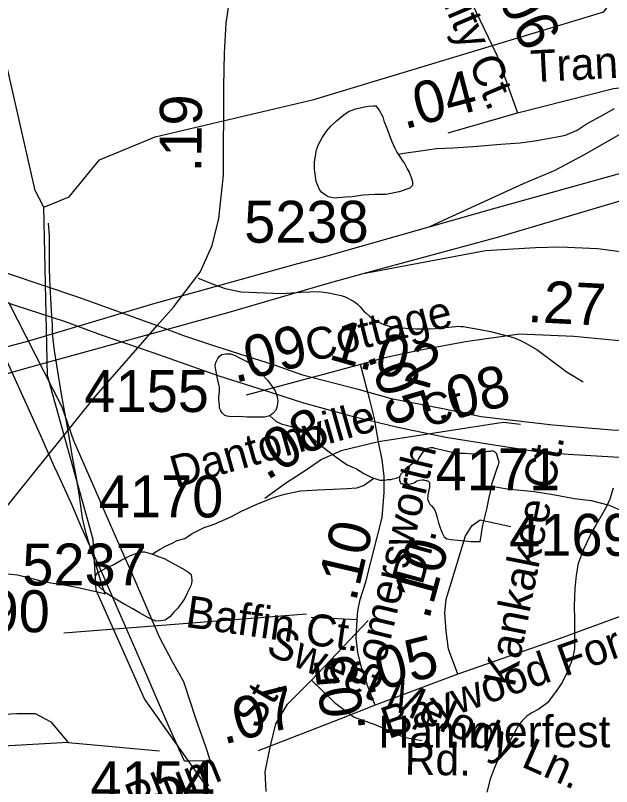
# Model space of a CAD drawing. Extents: x 2169602 to 2449496, y 721995 to 810662.
# Drawn here: x 2396320 to 2398099, y 797480 to 799779 of the extents above; entities that cross this region are included whole.
import ezdxf

# ---------------------------------------------------------------- set-up
doc = ezdxf.new("R2010")
doc.units = 0
doc.layers.add('Default', color=7, linetype='Continuous')

msp = doc.modelspace()

# ---------------------------------------------------------------- linework, layer by layer
at = {"layer": 'Default'}
for p, q in [((2397188.4, 797994.3), (2396464.8, 797937.6)), ((2397339.9, 797977.5), (2397202.8, 797984)), ((2397203.4, 797797.3), (2397373.3, 797974.6)), ((2397640.3, 797814.8), (2397394, 797722.3)), ((2396477.3, 797611.4), (2396184.4, 797594.2)), ((2396477.3, 797611.4), (2396750.5, 797586.8))]:
    msp.add_line(p, q, dxfattribs=at)
for points in [[(2396405.1, 799207.2), (2396379.1, 799256.9), (2396191.1, 800080.9), (2396072.1, 800611.5), (2396037.1, 800828.7)], [(2397623.6, 799980.6), (2397667.1, 799847.6), (2397757.1, 799660.2), (2397818.6, 799488.1)], [(2396848.5, 798983.4), (2396871.3, 799013.1), (2396906.9, 799092.7), (2396927.3, 799173.3), (2396940.9, 799303.1), (2396942.4, 799568), (2396944.5, 799666.5), (2396948.8, 799756.1), (2396958, 799816.4), (2396968.9, 799884.8), (2396980.5, 799945.6)], [(2396405.1, 799207.2), (2396480.2, 799238.4), (2396571, 799348.1), (2396737.1, 799416.9), (2397211.2, 799528.6), (2398076.1, 799789.8), (2398151.3, 799892.8)], [(2397554.8, 799148.4), (2397623.6, 799180.7), (2397836, 799278.1), (2397930.6, 799317.2), (2398018.5, 799364.5), (2398135.2, 799430.9), (2398287.1, 799527.8), (2398366, 799581.1), (2398521.2, 799685.1), (2398585.6, 799724.2), (2398595.1, 799729.4), (2398620.6, 799743.8)], [(2397818.6, 799488.1), (2398104.9, 799561.2), (2398193.7, 799571.1), (2398260.8, 799573), (2398391.1, 799537.5), (2398462.2, 799500), (2398545.1, 799438.7), (2398608.3, 799349.9), (2398742.5, 799144.4), (2398864.9, 798962.7), (2398898.5, 798893)], [(2397462.5, 799365.4), (2397466.6, 799359.5), (2397475, 799345.2), (2397481, 799337.4), (2397489, 799321.6), (2397494.9, 799311.4), (2397501.1, 799295.4), (2397505, 799283.5), (2397505.2, 799279.4), (2397505.2, 799271.7), (2397497.6, 799263.5), (2397465.2, 799253.4), (2397425.6, 799245.2), (2397393.2, 799244.8), (2397357.7, 799242.9), (2397325.5, 799238.4), (2397305.6, 799236.6), (2397271.6, 799234), (2397253.6, 799238.3), (2397241.3, 799246.3), (2397233.3, 799252), (2397227.5, 799260.2), (2397217.5, 799283.9), (2397215, 799305.8), (2397213.2, 799319.9), (2397213, 799341.8), (2397217.1, 799366), (2397218.7, 799377.9), (2397224.7, 799394), (2397236.5, 799416.2), (2397248.4, 799434.3), (2397262.6, 799449.9), (2397278, 799464.2), (2397300.1, 799482.4), (2397314.3, 799492.4), (2397336, 799500.5), (2397362, 799506.7), (2397373.7, 799508.6), (2397387.9, 799508.9), (2397396.1, 799508.9), (2397405.9, 799496.8), (2397416.2, 799477), (2397420.1, 799465.1), (2397428.5, 799443.1), (2397442.4, 799405.3), (2397452.9, 799383), (2397458.8, 799371.2), (2397462.5, 799365.4)], [(2397462.5, 799365.4), (2397486.7, 799369.4), (2397529, 799375.6), (2397576.7, 799381.8), (2397626.8, 799384.3), (2397686.6, 799388.6), (2397768.5, 799394.9), (2397826.5, 799399.5), (2397876.5, 799405.8), (2397942.3, 799418.2), (2397962, 799422.1), (2397996.3, 799436.4), (2398023.9, 799454.4), (2398074.2, 799482.5), (2398107.8, 799501)], [(2397554.8, 799148.4), (2397754.8, 799205.1), (2398512.4, 799416), (2398798.3, 799498.8)], [(2397611.3, 799428.9), (2397818.6, 799488.1)], [(2397358.4, 799009.7), (2397763.2, 799118.4), (2398299.3, 799277.7), (2398688.2, 799382), (2398860.6, 799432)], [(2395355.1, 799242.6), (2395483.4, 799218.7), (2395640.2, 799190.2), (2395732.9, 799171), (2395883.1, 799133.6), (2395992.3, 799104.3), (2396146.4, 799059.4), (2396301.6, 799008.2), (2396508.9, 798939.4), (2396743.6, 798854.3)], [(2397643, 796796.9), (2397442.1, 797053.6), (2397233.1, 797185.9), (2397032.2, 797226), (2396949.1, 797326.2), (2396906.1, 797458.2), (2396705.1, 797741.2), (2396561.2, 798065.7), (2396552.2, 798216.7), (2396416.2, 798705), (2396405.1, 799207.2)], [(2397358.4, 799009.7), (2397723.5, 799077.7), (2397871.9, 799086.7), (2397944.6, 799088.7), (2398056.9, 799084.1), (2398194.1, 799066.6), (2398376, 799039.8), (2398559, 799012.3), (2398652.2, 799004.3), (2398738.4, 799007.7), (2398822.4, 799020.5), (2398883.6, 799038.5), (2398949.7, 799061.3), (2399012.6, 799095.9), (2399120.1, 799184.7), (2399154.1, 799209.3)], [(2396417.9, 799159.4), (2396420.5, 799121.7), (2396420.7, 799053.5), (2396420.9, 799021.4), (2396423.2, 798969.6), (2396425.6, 798917.7), (2396427.7, 798881.6), (2396430.2, 798857.7), (2396429.7, 798835.5), (2396432.2, 798813.7), (2396436.3, 798779.8), (2396442.5, 798735.8), (2396446.6, 798711.6), (2396457, 798649.6), (2396471.6, 798568), (2396481.8, 798512), (2396490, 798462.1), (2396500.3, 798406.2), (2396510.7, 798346.2), (2396519.4, 798280.4), (2396529.2, 798238.3), (2396541.7, 798198.4), (2396560.2, 798140.4), (2396580.3, 798074.5), (2396588.5, 798054.6)], [(2393727.7, 798967.2), (2393806.4, 798937.7), (2393895.5, 798907.3), (2393994.7, 798875.9), (2394073.5, 798850.7), (2394160.7, 798819.8), (2394322.8, 798778.6), (2394425.4, 798749.4), (2394579.5, 798719.5), (2394694.5, 798696.6), (2394908.4, 798671.3), (2395084.1, 798656.4), (2395222, 798655), (2395369.2, 798660.5), (2395553.8, 798663.3), (2395797.4, 798685), (2395992.3, 798720.4), (2396192.5, 798764.3), (2396360.4, 798808.9), (2396730.4, 798919.4), (2397163.3, 799039.1), (2397250.8, 799062.3), (2397554.8, 799148.4)], [(2395411.2, 799149.2), (2395451.8, 799142.5), (2395632, 799110.5), (2395732.9, 799087.6), (2395895, 799042), (2396137.2, 798975.1), (2396318.1, 798914.7), (2396468.5, 798866.1), (2396573.3, 798827.7), (2396686.6, 798789.3)], [(2396743.6, 798854.3), (2396822.3, 798824.9), (2396911.3, 798794.5), (2397010.6, 798763), (2397089.3, 798737.9), (2397176.5, 798707), (2397338.6, 798665.8), (2397441.3, 798636.6), (2397595.3, 798606.7), (2397710.3, 798583.7), (2397924.2, 798558.4), (2398099.9, 798543.6), (2398237.8, 798542.2), (2398385, 798547.7), (2398569.6, 798550.5), (2398813.2, 798572.1), (2399008.1, 798607.5), (2399208.3, 798651.5), (2399376.3, 798696), (2399746.2, 798806.6), (2400179.1, 798926.3), (2400266.6, 798949.5), (2400570.6, 799035.6)], [(2396170.5, 798675.2), (2396355.1, 798728.5), (2396652.2, 798810.1), (2396958, 798894.6), (2397250.8, 798980.2), (2397358.4, 799009.7)], [(2396865.8, 798996), (2396917.9, 798974.4), (2396945.9, 798964.6), (2396994.1, 798955.2), (2397114.2, 798950.3), (2397158.2, 798952.8), (2397172.3, 798953.7), (2397226.1, 798955.6), (2397254.6, 798952.1), (2397292.3, 798944.3), (2397304.2, 798939.8), (2397314.1, 798935), (2397321.4, 798931.5), (2397329.1, 798926.7), (2397335.2, 798922.6), (2397340.9, 798918.3), (2397349.5, 798910.1), (2397359.3, 798898.7), (2397366.8, 798891.2), (2397376.4, 798882), (2397385, 798875.4), (2397391.7, 798871.1), (2397404.4, 798864.6), (2397416.7, 798858.9), (2397425.6, 798855.6), (2397436.9, 798852.1), (2397447.3, 798849.9), (2397462.5, 798848), (2397485.4, 798846.3), (2397515.4, 798844.7), (2397534, 798844.3), (2397556, 798844.5), (2397573.4, 798845.3), (2397613.3, 798849.7), (2397643.3, 798852.1), (2397649.9, 798852), (2397656.5, 798851.4), (2397667.1, 798849.6), (2397707.5, 798842.8), (2397737.6, 798837), (2397795.7, 798821.6), (2397811.2, 798816.5), (2397827.8, 798809.9), (2397839.9, 798803.9), (2397876.1, 798782.5), (2397916.4, 798752.9), (2397966.9, 798715.5), (2398014.7, 798686.3)], [(2396743.6, 798854.3), (2396791.8, 798909.4), (2396848.5, 798983.4)], [(2396299.2, 798924.3), (2396458.7, 798612.1), (2396493.4, 798511.5), (2396550.7, 798382.4), (2396590.4, 798290.6), (2396631.9, 798196), (2396672.9, 798104.3), (2396749.2, 797926.5), (2396788.4, 797852.9), (2396821.4, 797793.3), (2396857.4, 797683.8), (2396887.2, 797599), (2396901.2, 797556.5), (2396890.7, 797556.4), (2396838.2, 797555.8), (2396825.2, 797555.9), (2396809.2, 797590.6), (2396776.4, 797664), (2396740.4, 797746.3), (2396704.4, 797830.1), (2396620.7, 798020.3), (2396584.7, 798103.3), (2396518.7, 798250.6), (2396488.4, 798320.8), (2396440.4, 798425.1), (2396438.9, 798428.3), (2396396.4, 798525.9), (2396223.4, 798904.9)], [(2396299.2, 798924.3), (2396458.7, 798612.1), (2396493.4, 798511.5), (2396550.7, 798382.4), (2396590.4, 798290.6), (2396631.9, 798196), (2396672.9, 798104.3), (2396749.2, 797926.5), (2396788.4, 797852.9), (2396821.4, 797793.3), (2396857.4, 797683.8), (2396887.2, 797599), (2396901.2, 797556.5), (2396890.7, 797556.4), (2396838.2, 797555.8), (2396825.2, 797555.9), (2396809.2, 797590.6), (2396776.4, 797664), (2396740.4, 797746.3), (2396704.4, 797830.1), (2396620.7, 798020.3), (2396584.7, 798103.3), (2396518.7, 798250.6), (2396488.4, 798320.8), (2396440.4, 798425.1), (2396438.9, 798428.3), (2396396.4, 798525.9), (2396223.4, 798904.9)], [(2396686.6, 798789.3), (2396727.4, 798775.4), (2396815.3, 798744.2), (2396927.1, 798704.8), (2397084.6, 798654.5), (2397179.7, 798623.6), (2397320.7, 798585.2), (2397461.9, 798551.6), (2397604.5, 798521.7), (2397735.6, 798501), (2397882.8, 798478), (2397970.2, 798471.1), (2398139.3, 798460.9), (2398374.2, 798459.3), (2398571, 798470.3), (2398754.2, 798486), (2398884.7, 798505.3), (2398939.9, 798515.7), (2399104.1, 798545.4), (2399186.3, 798562.4), (2399370.9, 798615.6), (2399668, 798697.3), (2399973.8, 798781.8), (2400266.6, 798867.4)], [(2396686.6, 798789.3), (2396743.6, 798854.3)], [(2398670.5, 798738.2), (2398402.1, 798771.8), (2398160, 798804.4), (2398111.6, 798810.1), (2397986.5, 798821.4), (2397824.9, 798828.9), (2397663.8, 798805.4), (2397519.5, 798778.5), (2397422.2, 798758.4), (2397350.1, 798738.6)], [(2396588.4, 798677.1), (2396686.6, 798789.3)], [(2397079.5, 798585.2), (2397063.5, 798581.2), (2397035.4, 798581), (2397011.6, 798580.9), (2396987.6, 798582.9), (2396965.5, 798582.6), (2396951.3, 798584.7), (2396943.7, 798586.7), (2396937.4, 798594.6), (2396933.1, 798600.5), (2396929, 798608.4), (2396929, 798616.5), (2396926.9, 798634.3), (2396926.9, 798642.4), (2396929, 798656.3), (2396929.2, 798670.4), (2396922.8, 798696.5), (2396918.7, 798722.3), (2396916.5, 798734.5), (2396918.5, 798744.3), (2396920.4, 798748.4), (2396924.3, 798756.4), (2396928.8, 798762.6), (2396936.1, 798768.4), (2396948.2, 798770.5), (2396962.4, 798770.5), (2396976.3, 798764.7), (2396990.7, 798756.9), (2397014.5, 798744.7), (2397038.5, 798726.9), (2397072.9, 798691.3), (2397091, 798665.4), (2397095.1, 798659.5), (2397101, 798641.6), (2397102.9, 798629.6), (2397101, 798613.6), (2397097.3, 798601.6), (2397089.3, 798593.5), (2397079.5, 798585.2)], [(2397350.1, 798738.6), (2397251, 798711.4), (2397008.5, 798647.2)], [(2397403.6, 798508), (2397391, 798581.5), (2397378.1, 798633.2), (2397350.1, 798738.6)], [(2395913.6, 797895.8), (2395956.2, 797920.4), (2396129.7, 798120.9), (2396269.9, 798285.3), (2396555.3, 798639.2), (2396588.4, 798677.1)], [(2397079.5, 798585.2), (2397097.5, 798569.5), (2397113.7, 798561.4), (2397143.5, 798553.7), (2397171.8, 798540.1), (2397191.8, 798528.1), (2397217.7, 798510), (2397240, 798490.4), (2397256.2, 798478.2), (2397280, 798460.4), (2397310, 798438.8), (2397338.3, 798426.8), (2397360, 798413), (2397384, 798401.3), (2397390.1, 798399.1)], [(2397827.1, 798559.4), (2397775.3, 798564.9), (2397403.6, 798508)], [(2397403.6, 798508), (2397292.2, 798480.6), (2397234.1, 798454.9), (2397191.1, 798424.8), (2397126.6, 798383.9), (2397064.2, 798338.8)], [(2397339.9, 797977.5), (2397342.3, 798003.9), (2397349.4, 798037.4), (2397366.2, 798090.1), (2397415, 798282.4), (2397420.6, 798356.3), (2397420.6, 798404.3), (2397415, 798454.1), (2397403.6, 798508)], [(2397742.2, 798375.1), (2397742.4, 798381.2), (2397750.2, 798405.1), (2397758, 798429.1), (2397761.9, 798439.4), (2397763.9, 798447.2), (2397762.1, 798453.2), (2397758, 798467.2), (2397755.5, 798473.2), (2397751.6, 798477.1), (2397743.6, 798481.1), (2397737.9, 798479.2), (2397727.6, 798479.1), (2397708, 798472.8), (2397697.9, 798471), (2397685.8, 798470.8), (2397661.6, 798472.9), (2397647.5, 798472.6), (2397633.9, 798474.6), (2397619.6, 798476.4), (2397589.4, 798484.1), (2397571.8, 798488), (2397567.7, 798490.3), (2397559.5, 798489.9), (2397549.9, 798488.1), (2397543.7, 798484.2), (2397539.8, 798481.9), (2397531.8, 798471.8), (2397522, 798455.8), (2397520.1, 798450.1), (2397513.8, 798447.7), (2397501.9, 798439.9), (2397494.1, 798433.7), (2397485.7, 798427.7), (2397478.5, 798419.4), (2397470.3, 798411.7), (2397468.5, 798407.6), (2397466, 798403.5)], [(2396729.5, 798173.3), (2396735.6, 798177.6), (2396751.8, 798187.8), (2396766, 798195.8), (2396787.5, 798205.9), (2396803.3, 798214), (2396825.6, 798220), (2396847.6, 798234.1), (2396863.4, 798242.3), (2396883.2, 798252.3), (2396913, 798262.4), (2396961, 798282.7), (2396995, 798301.1), (2397038.9, 798321.2), (2397090.6, 798341.4), (2397122.9, 798351.5), (2397170.5, 798361.8), (2397222.4, 798364.1), (2397268.5, 798366.4), (2397310.6, 798368.5), (2397338.7, 798370.8), (2397358.8, 798377.1), (2397376, 798389.1), (2397390.1, 798399.1)], [(2397390.1, 798399.1), (2397408.2, 798393.2), (2397416.4, 798393.2), (2397422.3, 798393.5), (2397430.3, 798395.5), (2397440.2, 798395.6), (2397448, 798397.7), (2397456, 798399.7), (2397466, 798403.5)], [(2397466, 798403.5), (2397466, 798393.7), (2397468.1, 798387.7), (2397470.3, 798383.7), (2397474.2, 798383.6), (2397480.8, 798381.8), (2397486.7, 798381.7), (2397494.7, 798381.7), (2397502.3, 798383.8), (2397510.3, 798385.8), (2397518.5, 798391.9), (2397526.5, 798393.9), (2397534.1, 798394), (2397538, 798394.2), (2397544.1, 798392.1), (2397548.2, 798392.2), (2397552.1, 798390), (2397556.2, 798386.2), (2397556, 798380.1), (2397556.4, 798371.9), (2397554.2, 798364.1), (2397550.7, 798350.1), (2397550.5, 798346.1), (2397550.3, 798338), (2397550.5, 798334.3), (2397552.7, 798329.9), (2397556.6, 798322), (2397562.8, 798316.2), (2397571, 798306.1), (2397574.9, 798296.2), (2397578.8, 798282.2), (2397582.9, 798266.1), (2397587, 798254.2), (2397593.1, 798238.2), (2397599.3, 798224.3), (2397607.3, 798218.6), (2397621, 798216.6), (2397639.5, 798214.6), (2397661.2, 798212.9), (2397679.3, 798211), (2397693.2, 798210.9), (2397703.5, 798211), (2397707.3, 798209.2), (2397714.9, 798259.1), (2397726.6, 798307.2), (2397734.4, 798341.4), (2397742.2, 798375.1)], [(2399190.5, 798403.5), (2399112.1, 798348.7), (2398989.7, 798298.5), (2398750.1, 798215.4), (2398203.8, 798016.1), (2397943.2, 797920.8), (2397640.3, 797814.8)], [(2397742.2, 798375.1), (2397788.1, 798367.3), (2397868.5, 798360), (2397918.6, 798352), (2397988.7, 798338.6), (2398038.5, 798332.7), (2398092.4, 798319.3), (2398132.4, 798301.4), (2398174.7, 798287.8), (2398244.8, 798266.2), (2398290.9, 798252.3), (2398354.9, 798228.9), (2398415.2, 798205.2), (2398487.2, 798191.4), (2398567.3, 798172), (2398617.2, 798160.4), (2398653, 798148.5), (2398693.6, 798136.7), (2398725.4, 798129), (2398761.5, 798121.1), (2398781.4, 798115.3), (2398797.4, 798111.3)], [(2398104, 798369.4), (2398094.4, 798337.1), (2398082.5, 798311), (2398052.5, 798259.1), (2398040.6, 798239), (2398032.8, 798222.7), (2398015, 798184.9), (2397999.4, 798144.6), (2397993.7, 798110.6), (2397989.6, 798070.7), (2397988.1, 798018.5), (2397988.6, 797976.7), (2397988.6, 797928.9), (2397988.6, 797890.7), (2397982.8, 797860.7), (2397969.1, 797824.7), (2397951.4, 797790.5), (2397933.6, 797764.4), (2397908, 797730.1), (2397879.9, 797710), (2397861.6, 797700.2), (2397846, 797690), (2397832.1, 797675.9), (2397822.1, 797664), (2397814.3, 797649.8), (2397786.8, 797599.5), (2397760.7, 797561.7), (2397748.8, 797533.5), (2397737.2, 797501.6), (2397727.5, 797463.3)], [(2397640.3, 797814.8), (2397612.3, 797889.2), (2397605.5, 797943.4), (2397602.1, 797997.5), (2397605.5, 798038.2), (2397629.2, 798116.1), (2397663.1, 798227.8), (2397683.4, 798258.3), (2397707.1, 798275.2), (2397798.4, 798254.9)], [(2395895.4, 798198.8), (2395913.8, 798196.8), (2395947.9, 798192.8), (2395976, 798187.4), (2396004.1, 798179.5), (2396035.6, 798165.7), (2396063.9, 798151.8), (2396106.4, 798138.1), (2396157.8, 798126.2), (2396212.2, 798120.4), (2396288.3, 798115), (2396326.2, 798111.3), (2396358.2, 798103.6), (2396395.9, 798093.8), (2396426.1, 798087.7), (2396459.9, 798082.1), (2396502.3, 798074.1), (2396582.3, 798056.7), (2396588.5, 798054.6)], [(2396729.5, 798173.3), (2396747.7, 798165.7), (2396763.7, 798159.6), (2396781.9, 798149.5), (2396807.8, 798135.9), (2396826, 798125.9), (2396837.9, 798118), (2396844.3, 798112.2), (2396846.1, 798106.2), (2396846.3, 798091.9), (2396844.3, 798080.1), (2396834.2, 798058.1), (2396824.6, 798040.1), (2396814.5, 798026.2), (2396804.5, 798011.9), (2396792.8, 797999.9), (2396780.7, 797985.9), (2396767, 797975.8), (2396753.2, 797973.8), (2396739.1, 797973.5), (2396716.9, 797983.4), (2396690.7, 797997.5), (2396670.6, 798009.4), (2396646.6, 798023.2), (2396622.6, 798037), (2396590.6, 798056.8), (2396570.5, 798076.5), (2396564.4, 798082.7), (2396560.5, 798092.6), (2396558.4, 798100.6), (2396560.5, 798110.4), (2396566, 798118.5), (2396574.4, 798122.5), (2396590.2, 798130.7), (2396611.8, 798140.8), (2396635.9, 798155), (2396663.6, 798169.1), (2396683.9, 798175.3), (2396699.9, 798179.4), (2396705.9, 798179.3), (2396729.5, 798173.3)], [(2397394, 797722.3), (2397371, 797781.1), (2397351.8, 797838.6), (2397342.3, 797879.3), (2397337.5, 797922.5), (2397339.9, 797977.5)], [(2397068.1, 797464.9), (2397065.6, 797524), (2397080.4, 797597.9), (2397097.6, 797666.8), (2397132.1, 797725.9), (2397203.4, 797797.3)], [(2397203.4, 797797.3), (2397272.4, 797730.8), (2397331.4, 797686.5), (2397395.4, 797664.3), (2397479.1, 797627.4), (2397533.3, 797617.6)], [(2397394, 797722.3), (2397287.9, 797680.5), (2397044.6, 797586.9)], [(2395946.3, 797673.1), (2396061.3, 797682.8), (2396324.7, 797697.6), (2396378.8, 797697.6), (2396425.6, 797673), (2396477.3, 797611.4)]]:
    msp.add_lwpolyline(points, dxfattribs=at)

# ---------------------------------------------------------------- texts
for s, height, rotation, p in [('Amity Ct.', 95, 293.0309, (2397533, 799963.4)), ('.06', 125, 296.3888, (2397737.9, 799873.2)), ('Tranquility', 95, 2.9342, (2397859.7, 799579.6)), ('.04', 125, 14.7301, (2397480.9, 799439)), ('.19', 125, 89.6605, (2396875.1, 799310.6)), ('.27', 125, 357.0877, (2397846.8, 798865.3)), ('Cottage', 95, 14.1568, (2397199, 798745)), ('.09', 125, 14.2725, (2396975.3, 798682.7)), ('1.02', 125, 344.1195, (2397251.3, 798755.6)), ('.05', 125, 289.6111, (2397369.3, 798765.3)), ('.08', 125, 14.2725, (2397579.9, 798562.9)), ('Ct.', 95, 15.9651, (2397545.5, 798549.4)), ('Dantonville', 95, 15.9651, (2396798.4, 798370.1)), ('.08', 125, 31.7981, (2397069.9, 798390.9)), ('Kankakee Ct.', 95, 78.6949, (2397809.6, 797773.5)), ('Somersworth', 95, 76.5095, (2397402.9, 797761.7)), ('.10', 125, 76.9395, (2397336, 798027.9)), ('Dr.', 95, 74.751, (2397534.6, 798077.9)), ('.10', 125, 74.7835, (2397554.2, 797974.3)), ('Baffin Ct.', 95, 351.8304, (2396825, 797956.3)), ('Baywood Forest Dr.', 95, 19.5099, (2397433.1, 797621)), ('Sweet Melody Ln.', 95, 336.1851, (2397064, 797877.4)), ('.05', 125, 14.2725, (2397365.9, 797756.1)), ('.05', 125, 98.2067, (2397365.7, 797649.7)), ('.07', 125, 14.2725, (2396941.7, 797604.9)), ('St.', 95, 59.7546, (2397046.1, 797646.9)), ('Hammerfest', 95, 0.1043, (2397404.1, 797595.9)), ('Rd.', 95, 359.1903, (2397481.5, 797515.5)), ('Plum', 95, 21.7353, (2396673.1, 797392.7))]:
    msp.add_text(s, height=height, rotation=rotation, dxfattribs=at).set_placement(p)
for s, p in [('5238', (2397002.8, 799101.3)), ('4155', (2396525.8, 798596.6)), ('4171', (2397574, 798363.1)), ('4170', (2396568.8, 798282.5)), ('4169', (2397793.5, 798167.9)), ('5237', (2396340.6, 798079.5)), ('4190', (2396051.1, 797940.1)), ('4154', (2396544.2, 797430.5))]:
    msp.add_text(s, height=125, dxfattribs=at).set_placement(p)

doc.saveas('drawing.dxf')
